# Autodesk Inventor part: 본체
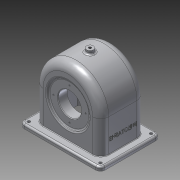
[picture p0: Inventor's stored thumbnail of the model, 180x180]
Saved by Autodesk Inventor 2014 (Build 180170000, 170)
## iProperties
Created: 2016-02
Part Number: 본체
Material: 알루미늄 6061
Document SubType Name: Modeling
Designer: Owner
Density: 2.71 g/cm^3
Appearance: 알루미늄 - 평지
Mass: 757.291 g
Surface Area: 1005.83 cm^2
Volume: 279.443 cm^3
Author: Owner
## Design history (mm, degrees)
sketch "스케치1"
  geometry: L1 (-57, 0)-(-57, -64); L2 (-57, -64)-(57, -64); L3 (57, -64)-(57, 0); A1 r 57 centre (0, 0) between (57, 0) and (-57, 0); 1 further point
  constraints: 6 end point, 2 point on circle, 2 tangent, 1 centre point, 1 coincident, 1 horizontal, 1 parallel, 1 vertical
  dimensions: "d0" = 57 radius of A1; "d1" = 64 distance from line of point (0, 0) L2
extrude "돌출1" new body sketch "스케치1" stored distance "d2" = 77; taper "d3" = 0 deg
fillet "모깎기1" dims "d4" = 14
feature "쉘1" dims "d5" = 5
sketch "스케치2"
  geometry: L1 (-43, -64)-(43, -64) reference; C1 r 31 at (0, -4); A1 r 43 centre (0, 0) between (43, 0) and (-43, 0) reference
  constraints: 1 centre point, 1 vertical alignment
  dimensions: "d6" = 31 radius of C1; "d7" = 60 distance from line of L1 C1.centre
extrude "돌출2" join sketch "스케치2" distance "d8" = 10; taper "d9" = 0 deg
sketch "스케치3"
  geometry: L1 (-64, 33.5)-(0, 33.5) reference; L2 (-4, 38.5)-(-4, 19.5); L3 (-64, -24.5)-(-64, 24.5) reference; L4 (0, 33.5)-(43, 33.5) reference; L5 (-4, 19.5)-(24, 19.5); L6 (24, 19.5)-(35.747, 33.5); L7 (0, 38.5)-(43, 38.5) reference; L8 (33.416, 38.5)-(30.899, 35.5); L9 (30.899, 35.5)-(-4, 35.5); L10 (35.747, 33.5)-(33.416, 38.5); L11 (-64, 38.5)-(0, 38.5) reference; L12 (33.416, 38.5)-(-4, 38.5); 1 further point
  constraints: 14 end point, 4 point on line, 2 parallel, 1 collinear, 1 perpendicular
  dimensions: "d10" = 60 distance between parallel lines of L3 L2; "d17" = 3 distance between parallel lines of L7 L9; "d18" = 16 distance between parallel lines of L5 L9; "d19" = 50 deg angle of L5 L6; "d20" = 5 distance between parallel lines of L8 L6; "d21" = 56 diameter of L5.end L2
revolve "회전1" stored, may be unused: angle "d23" = 90 deg
revolve "회전2" stored, may be unused: angle "d24" = 90 deg
hole "구멍1" diameter "d27" = 40; stored, may be unused: countersink angle "d31" = 90 deg, drill point angle "d33" = 118 deg; dims "d25" = 10, "d26" = 10, "d28" = 6, "d29" = 4, "d30" = 2, "d32" = 8
sketch "스케치4"
  geometry: L1 (100, -63)-(100, -14) reference; L2 (0, 0)-(86, 0) reference; L3 (-14, -63)-(-14, -14) reference; L4 (86, -77)-(0, -77) reference; L5 (-27, 13.5)-(113, 13.5); L6 (113, 13.5)-(113, -90.5); L7 (113, -90.5)-(-27, -90.5); L8 (-27, -90.5)-(-27, 13.5); L9 (-27, 13.5)-(113, -90.5); L10 (113, 13.5)-(-27, -90.5); A1 r 14 centre (86, -63) between (86, -77) and (100, -63) reference; A2 r 14 centre (86, -14) between (100, -14) and (86, 0) reference; A3 r 14 centre (0, -14) between (0, 0) and (-14, -14) reference; A4 r 14 centre (0, -63) between (-14, -63) and (0, -77) reference; 1 further point
  constraints: 12 end point, 2 midpoint, 2 parallel, 1 horizontal, 1 perpendicular
  dimensions: "d34" = 140 distance of L6.end L7.end; "d35" = 104 distance of L5.end L6.end
extrude "돌출3" join sketch "스케치4" distance "d36" = 7; taper "d37" = 0 deg
hole "구멍2" diameter "d40" = 5; stored, may be unused: countersink angle "d44" = 90 deg, drill point angle "d46" = 118 deg; dims "d38" = 8, "d39" = 8, "d41" = 6, "d42" = 4, "d43" = 2, "d45" = 8
node "작업 평면1"
sketch "스케치5"
  geometry: C1 r 2.5 at (8, -8) reference; C2 r 2.5 at (8, -96) reference; C3 r 6 at (70, -52); 1 further point
  constraints: 1 centre point, 1 coincident
  dimensions: "d48" = 6 radius of C3
extrude "돌출4" join sketch "스케치5" stored distance "d49" = 0; taper "d50" = 0 deg
sketch "스케치6"
  geometry: C1 r 20 at (0, 0) reference; 2 further points
  constraints: 1 vertical alignment
  dimensions: "d60" = 28 distance of point (0, 28) C1.centre
sketch "스케치7"
  geometry: C1 r 20 at (0, 0) reference; 2 further points
  constraints: 1 vertical alignment
  dimensions: "d61" = 24 distance of C1.centre point (0, 24)
hole "구멍4" sketch "스케치7" at (0, 24) diameter "d62" = 2.459; stored, may be unused: countersink angle "d66" = 90 deg, drill point angle "d68" = 118 deg; dims "d63" = 6, "d64" = 4, "d65" = 2, "d67" = 8
hole "구멍5" sketch "스케치6" diameter "d69" = 2.459; stored, may be unused: countersink angle "d73" = 90 deg, drill point angle "d75" = 118 deg; dims "d70" = 7, "d71" = 4, "d72" = 2, "d74" = 9
chamfer "모따기1" distance "d82" = 1; stored, may be unused: second distance "d83" = 2, angle "d84" = 45 deg
fillet "모깎기2" dims "d85" = 8, "d86" = 1
fillet "모깎기3" dims "d87" = 3
node "작업 평면2"
sketch "스케치8"
  geometry: L1 (-14, 0)-(-14, -56) reference; L2 (-19.5, -64)-(68.5, -64) reference; 2 further points
  constraints: 1 other
  dimensions: "d89" = 38.5 distance from line of L1 point (24.5, -34); "d90" = 30 distance from line of point (24.5, -34) L2
feature "엠보싱1" sketch "스케치8" dims "d91" = 0.5, "d92" = 0
sketch "스케치9"
  geometry: L1 (-51, 0)-(-51, -64); L2 (-52, -64)-(-52, 0) reference; L3 (52, 0)-(52, -64) reference; L4 (52, -64)-(51, -64); L5 (-51, -64)-(-52, -64); L6 (51, 0)-(51, -64); A1 r 51 centre (0, 0) between (51, 0) and (-51, 0); A2 r 52 centre (0, 0) between (52, 0) and (-52, 0) reference; 1 further point
  constraints: 8 end point, 2 perpendicular, 2 point on circle, 2 tangent, 1 centre point, 1 coincident, 1 collinear, 1 vertical
  dimensions: "d93" = 51 radius of A1
extrude "돌출5" join sketch "스케치9" stored distance "d95" = 67; taper "d96" = 0 deg
hole "구멍6" diameter "d99" = 4.459; stored, may be unused: countersink angle "d103" = 90 deg, drill point angle "d105" = 118 deg; dims "d97" = 10, "d98" = 10, "d100" = 7, "d101" = 4, "d102" = 2, "d104" = 9
node "솔리드1"
mirror "대칭1"
mirror "대칭2"
pattern_circular "원형 패턴1" dims angle "d77" = 360 deg
pattern_circular "원형 패턴2" dims angle "d80" = 360 deg
other parameters: "d47" = -127, "d88" = 0.5
